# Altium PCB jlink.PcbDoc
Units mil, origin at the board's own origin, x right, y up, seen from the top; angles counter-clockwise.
Board outline 2620 x 1025 mil, 2 copper layers (Top Layer, Bottom Layer); 30 components, 28 nets, 122 pads, 66 vias.
Unrouted connection lines stored in the file: 1.
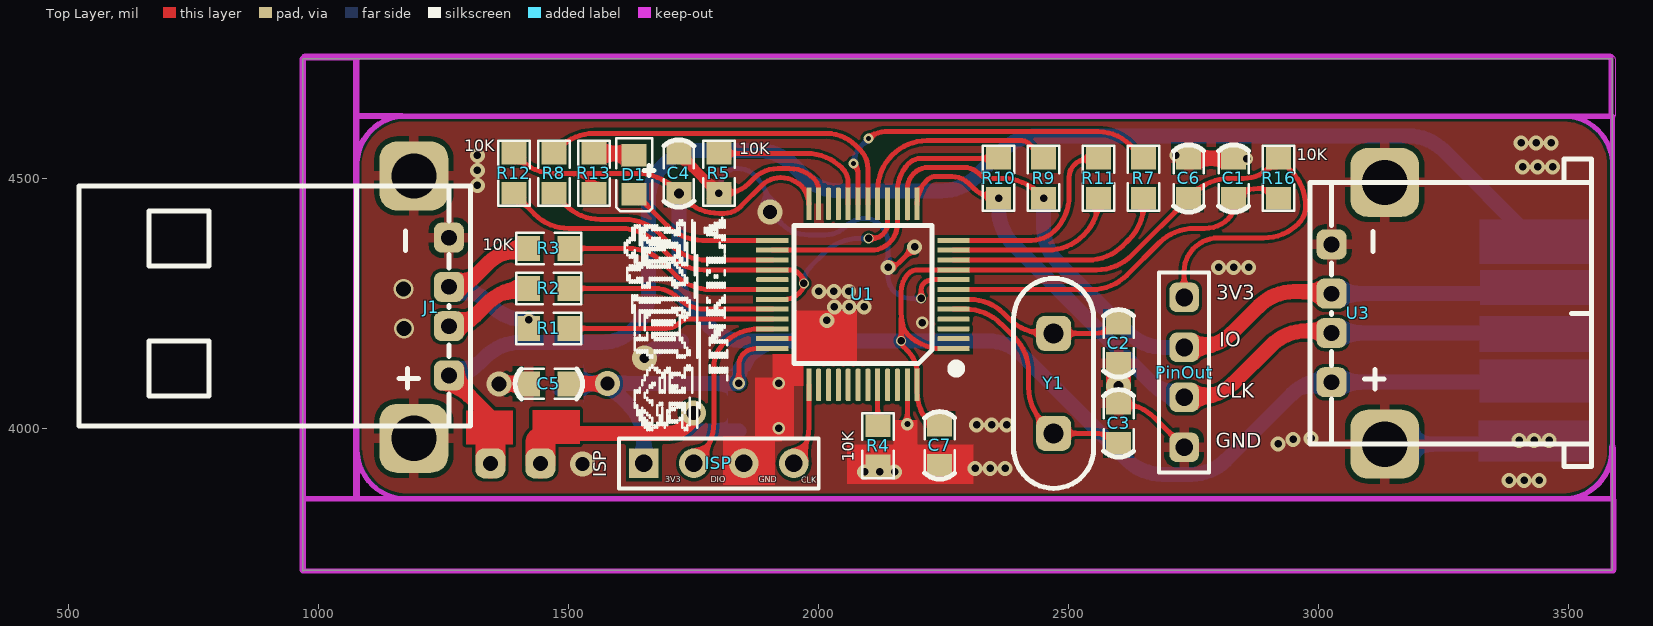
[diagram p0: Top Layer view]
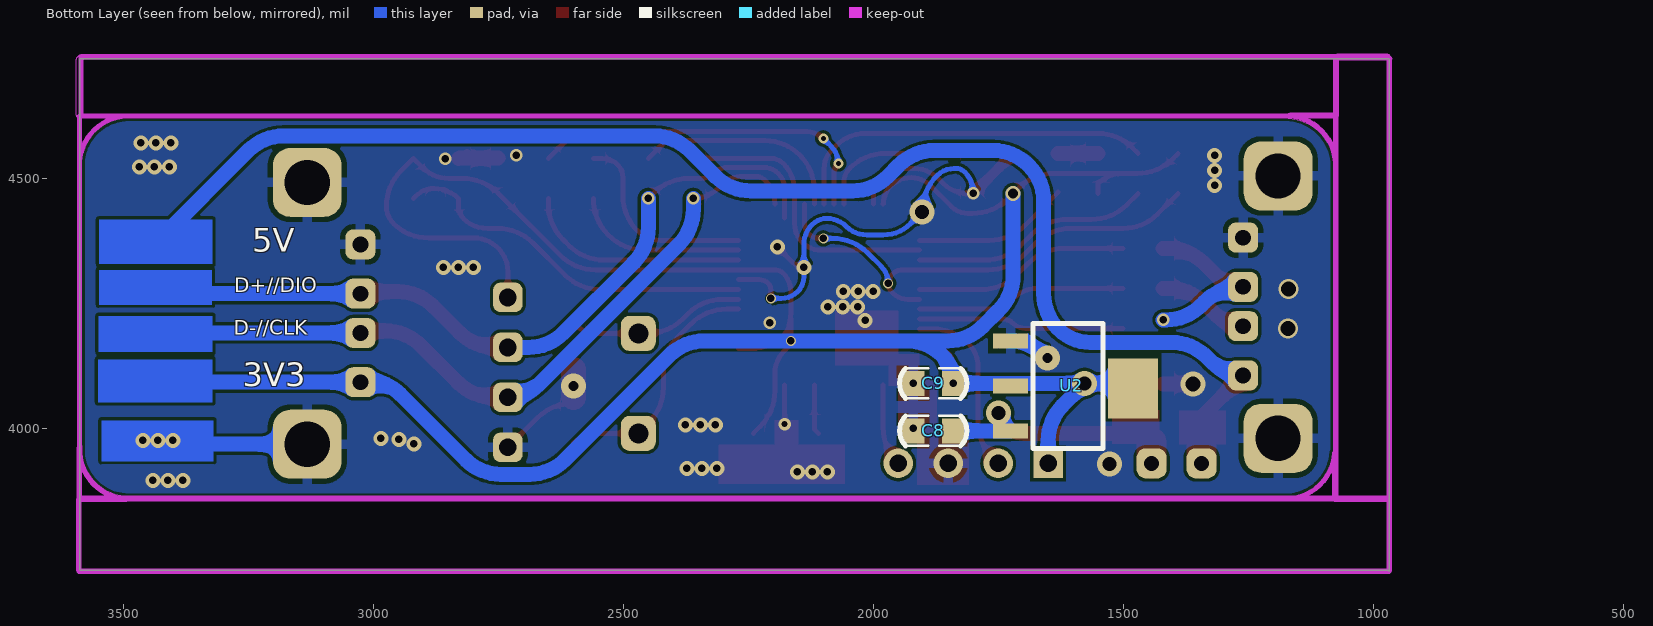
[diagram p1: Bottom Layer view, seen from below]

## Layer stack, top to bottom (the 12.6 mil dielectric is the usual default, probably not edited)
Top Solder: solder mask 0.4, Solder Resist, Dk 3.5
Top Layer: signal copper 1.4
Dielectric1: dielectric 12.6, FR-4, Dk 4.8
Bottom Layer: signal copper 1.4
Bottom Solder: solder mask 0.4, Solder Resist, Dk 3.5

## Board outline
969,3716 969,4741 3589,4741 3589,3717 970,3717
cut-out: 3589,4534 ccw(c3490.5,4527.5) 3484,4626 3589,4626
cut-out: 966.45,3712.45 965.45,3713.45 965.47,3713.44 cw(c969,3717) 963.99,3717 963.99,3860 cw(c969,3860) 969,3865.01 3589,3865.01 cw(c3589,3860) 3592.56,3863.53 3592.55,3863.55 3593.55,3862.55 3593.53,3862.56 cw(c3590,3859) 3595.01,3859 3595.01,3717 cw(c3590,3717) 3593.53,3713.44 3593.55,3713.45 3592.55,3712.45 3592.56,3712.47 cw(c3589,3716) 3589,3710.99 970,3710.99 cw(c970,3716)
cut-out: 966.45,3712.45 965.45,3713.45 965.47,3713.44 cw(c969,3717) 963.99,3717 963.99,4741 cw(c969,4741) 965.47,4744.56 965.45,4744.55 968.45,4747.55 968.44,4747.53 cw(c972,4744) 972,4749.02 1074,4749.02 cw(c1074,4744) 1077.56,4747.53 1077.55,4747.55 1079.55,4745.55 1079.53,4745.56 cw(c1076,4742) 1081.02,4742 1081.02,3860 cw(c1076,3860) 1070.98,3860 1070.98,4738.98 974.08,4738.98 974.01,4738.92 974.01,3719.01 cw(c970,3716) 975.01,3716 cw(c970,3716)
cut-out: 965.47,3713.44 cw(c969,3717) 963.99,3717 963.99,4741 cw(c969,4741) 965.47,4744.56 965.45,4744.55 968.45,4747.55 968.44,4747.53 cw(c972,4744) 972,4749.02 1074,4749.02 cw(c1074,4744) 1077.56,4747.53 1077.55,4747.55 1079.55,4745.55 1079.53,4745.56 cw(c1076,4742) 1081.02,4742 1081.02,3860 cw(c1076,3860) 1076,3854.99 974.01,3854.99 974.01,3719.01 cw(c970,3716) 975.01,3716 cw(c970,3716) 966.45,3712.45
cut-out: 972.55,4737.45 974.08,4738.98 1070.98,4738.98 1070.98,4626 ccw(c1076,4626) 1076,4620.98 3589,4620.98 ccw(c3589,4626) 3592.56,4622.47 3592.55,4622.45 3593.55,4623.45 3593.53,4623.44 ccw(c3590,4627) 3595.01,4627 3595.01,4740 ccw(c3590,4740) 3593.53,4743.56 3593.55,4743.55 3589.55,4747.55 3589.56,4747.53 ccw(c3586,4744) 3586,4749.02 972,4749.02 ccw(c972,4744) 968.44,4747.53 968.45,4747.55 965.45,4744.55 ccw(c969,4741)
cut-out: 3589,4534 ccw(c3490.5,4527.5) 3484,4626 3589,4626
cut-out: 3497,3854.99 cw(c3497,3860) 3496.67,3865 ccw(c3490.5,3958.5) 3583.98,3952.17 3583.98,3965 cw(c3589,3965) 3589,3970.01 cw(c3589,3965) 3594,3965.33 cw(c3490.5,3958.5) 3594.23,3958.5 cw(c3490.5,3958.5) 3594.01,3951.84 3594.01,3862.01 cw(c3590,3859) 3595.01,3859 cw(c3590,3859) 3586.99,3854.99
cut-out: 1183,3860 cw(c1176.5,3958.5) 1078,3952 1078,3860
cut-out: 1070.98,4534.16 1070.98,4738.98 974.08,4738.98 972.55,4737.45 cw(c969,4741) 965.45,4744.55 968.45,4747.55 968.44,4747.53 cw(c972,4744) 972,4749.02 1074,4749.02 cw(c1074,4744) 1077.56,4747.53 1077.55,4747.55 1079.55,4745.55 1079.53,4745.56 cw(c1076,4742) 1081.02,4742 1081.02,4631.02 1168,4631.02 cw(c1168,4626) 1173.02,4626 cw(c1168,4626) 1168.33,4621 ccw(c1174.5,4527.5) 1081.02,4533.83 1081.02,4521 cw(c1076,4521) 1071,4520.67 cw(c1174.5,4527.5)

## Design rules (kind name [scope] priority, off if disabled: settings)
Clearance [All] p1: gap=6 ignorepadtopadclearanceinfootprint=FALSE except(0: Arc-Hole Track-Hole SMDPad-Hole THPad-Hole Via-Hole Fill-Hole Poly-Hole Region-Hole Text-Hole)
HoleSize [All] p1: absolutevalues=TRUE maxlimit=100 minlimit=12 maxpercent=80.000 minpercent=20.000
HoleToHoleClearance [All] p1: gap=5 allowstackedmicrovias=TRUE
MinimumSolderMaskSliver [All] p1: minsoldermaskwidth=0
PolygonConnect PolygonConnect_1 [isVia] p1: connectstyle=Direct reliefconductorwidth=10 reliefentries=4 polygonreliefangle="90 Angle" airgapwidth=10
PolygonConnect [All] p2: connectstyle=Relief reliefconductorwidth=20 reliefentries=4 polygonreliefangle="90 Angle" airgapwidth=10
RoutingVias [All] p1: holewidth=15 width=25 viastyle="Through Hole" minholewidth=15 minwidth=20 maxholewidth=200 maxwidth=50
SilkToSilkClearance [All] p1: silktosilkclearance=0
SilkToSolderMaskClearance [IsPad] p1: minsilkscreentomaskgap=0 clearancetoexposedcopper=TRUE
SolderMaskExpansion [All] p1: expansion=4
Width [All] p1: maxlimit=100 minlimit=6 preferedwidth=10
25 further rules are at their usual default settings.

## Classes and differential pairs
component class jlink: C1 C2 C3 C4 C5 C6 C7 D1 ISP J1 PinOut R1 R2 R3 R4 R5 R7 R8 R9 R10 R11 R12 R13 R16 U1 U2 Y1

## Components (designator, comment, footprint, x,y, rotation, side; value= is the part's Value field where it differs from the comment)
C1 "104" 0805_cap 2831,4501 r90 top
C2 "22pF" 0805_cap 2601,4171 r270 top
C3 "22pF" 0805_cap 2601,4011 r90 top
C4 "104" 0805_cap 1721,4511 r90 top
C5 "104" 0805_cap 1461,4090 r180 top
C6 "104" 0805_cap 2741,4501 r90 top
C7 "104" 0805_cap 2243,3967 r270 top
C8 "104" 0805_cap 1881,3996 r0 bottom
C9 "104" 0805_cap 1881,4091 r0 bottom
D1 "" LED-0805 1631,4507 r270 top
ISP "" HDR1X4#1 1651,3931 r0 top
J1 "" USB_A公头 1011,4251 r0 top
PinOut "" HDR1X4#2 2732,4263 r270 top
R1 "100" 0805 1461,4201 r0 top
R2 "100" 0805 1461,4281 r0 top
R3 "10K" 0805 1461,4361 r180 top
R4 "10K" 0805 2120,3966 r270 top
R5 "10K" 0805 1801,4511 r270 top
R7 "100" 0805 2651,4501 r270 top
R8 "100" 0805 1471,4511 r270 top
R9 "100" 0805 2451,4501 r90 top
R10 "100" 0805 2361,4501 r90 top
R11 "100" 0805 2561,4501 r270 top
R12 "10K" 0805 1391,4511 r90 top
R13 "100" 0805 1551,4511 r270 top
R16 "10K" 0805 2921,4501 r90 top
U1 "f103c8" LQFP48S 2271,4161 r180 top
U2 "" "AMS1117 3V3 SOT23" 1541,4211 r270 bottom
U3 "" USB_A1ĸ 3192,4250 r180 top
Y1 "" XTAL-8M 2471,4091 r90 top

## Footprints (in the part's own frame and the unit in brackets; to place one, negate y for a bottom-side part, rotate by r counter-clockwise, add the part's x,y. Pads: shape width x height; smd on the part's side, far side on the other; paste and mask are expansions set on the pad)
0805 [mil]
  rect 45x50 smd: 1(-40,0) 2(40,0)
  silkscreen extent -65,-31 65,31, body extent -50,-20 50,20, height 25
0805_cap [mil]
  rect 45x50 smd: 1(-40,0) 2(40,0)
  silkscreen extent -67,-30 67,30, body extent -50,-20 50,20, height 25
"AMS1117 3V3 SOT23" [mil]
  rect 30x70 smd: 1(35,-185) 2(125,-185) 3(215,-185)
  rect 120x100 smd: 2(130,60)
  silkscreen extent 0,-140 250,0, body extent 20,-160 230,20, height 35
HDR1X4#1 [mm] "Connector; Header; 4 Position"
  rect 1.5x1.5 hole 0.9: 1(0,0)
  round 1.5 hole 0.9: 2(2.54,0) 3(5.08,0) 4(7.62,0)
  silkscreen extent -1.27,-1.27 8.89,1.27
HDR1X4#2 [mm] "Connector; Header; 4 Position"
  rrect50% 1.5x1.5 hole 0.9: 1(0,0) 2(2.54,0) 3(5.08,0) 4(7.62,0)
  silkscreen extent -1.27,-1.27 8.89,1.27
LED-0805 [mil]
  rect 45x50 smd: 1(-40,0) 2(37.5,0)
  silkscreen extent -75,-35 72,40, body extent -40,-20 40,20, height 30
LQFP48S [mil] "DPIN-0.5"
  rect 65x10 smd: 1(0.42,0.29) 5(0.42,-78.45) 6(0.42,-98.13) 7(0.42,-117.82) 8(0.42,-137.5) 9(0.42,-157.19) 10(0.42,-176.87) 11(0.42,-196.56) 12(0.42,-216.24) 25(362.63,-216.24) 26(362.63,-196.56) 27(362.63,-176.87) 28(362.63,-157.19) 30(362.63,-117.82) 31(362.63,-98.13) 32(362.63,-78.45) 33(362.63,-58.76) 34(362.63,-39.08) 35(362.63,-19.39) 36(362.63,0.29)
  rrect50% 65x10 smd: 2(0.42,-19.39) 3(0.42,-39.08) 4(0.42,-58.76) 29(362.63,-137.5)
  rect 10x65 smd: 13(73.26,-289.08) 14(92.94,-289.08) 15(112.63,-289.08) 16(132.31,-289.08) 17(152,-289.08) 18(171.68,-289.08) 19(191.37,-289.08) 20(211.05,-289.08) 23(270.11,-289.08) 24(289.79,-289.08) 37(289.79,73.13) 44(152,73.13) 47(92.94,73.13) 48(73.26,73.13)
  rrect50% 10x65 smd: 21(230.74,-289.08) 22(250.42,-289.08) 38(270.11,73.13) 39(250.42,73.13) 40(230.74,73.13) 41(211.05,73.13) 42(191.37,73.13) 43(171.68,73.13) 45(132.31,73.13) 46(112.63,73.13)
  silkscreen extent -10,-246 319,46, body extent 1,-289 366,71, height 30
USB_A1ĸ [mil]
  rrect50% 60x60 hole 31.5: 1(165,156.59) 2(165,58.16) 3(165,-20.58) 4(165,-119)
  rrect50% 137.8x137.8 hole 90.55: 5(58.7,280.61) 5(58.7,-243.02)
  silkscreen extent -355,-290 208,325, body extent -349,-292 208,330, height 297
USB_A公头 [mil] "USB_A公头"
  rrect50% 60x60 hole 31.5: 1(250,-144) 2(250,-45.58) 3(250,33.16) 4(250,131.59)
  rrect50% 137.8x137.8 hole 90.55: 5(180,-270) 5(180,255)
  silkscreen extent -490,-245 293,235
XTAL-8M [mil]
  rrect50% 70x70 hole 40: 1(-100,0) 2(100,0)
  silkscreen extent -210,-80 210,80, body extent -210,-80 210,80, height 110

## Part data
C1 C2 C3 C4 C5 C6 C7 C8 C9: library part Cap, "Capacitor"
D1: library part LED2, "Typical RED, GREEN, YELLOW, AMBER GaAs LED"
ISP PinOut: library part "Header 4", "Header, 4-Pin"
J1: library part USB, "USB-A"
R1 R2 R3 R4 R5 R7 R8 R9 R10 R11 R12 R13 R16: library part Res2, "Resistor"
U1: library part STM32F103C8T6, "STM32 ARM-based 32-bit MCU with 64 Kbytes Flash, 48-pin LQFP, Industrial Temperature"
U2: library part "AMS1117 3V3"
U3: library part USB_ĸ, "USB_ĸ"
Y1: library part XTAL, "Crystal Oscillator"

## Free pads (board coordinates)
  rrect60% 60x60 hole 30: 2(1344,3931) 3(1444,3931)

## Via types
v1: diameter 30, hole 15, Top Layer to Bottom Layer, 39 vias
v2: diameter 25, hole 15, Top Layer to Bottom Layer, 10 vias
v3: diameter 20, hole 15, Top Layer to Bottom Layer, 4 vias
v4: diameter 50, hole 28, Top Layer to Bottom Layer, 4 vias
v5: diameter 40, hole 30, Top Layer to Bottom Layer, 2 vias
v6: diameter 20, hole 10, Top Layer to Bottom Layer, 2 vias
v7: diameter 50, hole 20, Top Layer to Bottom Layer, 2 vias
v8: diameter 30, hole 20, Top Layer to Bottom Layer, 1 vias
v9: diameter 25, hole 12, Top Layer to Bottom Layer, 1 vias
v10: diameter 50, hole 30, Top Layer to Bottom Layer, 1 vias

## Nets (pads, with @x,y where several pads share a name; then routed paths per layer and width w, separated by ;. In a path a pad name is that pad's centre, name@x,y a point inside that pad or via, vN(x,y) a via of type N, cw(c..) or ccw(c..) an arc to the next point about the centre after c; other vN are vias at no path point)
3V3: C4.1 C5.1 C6.1 C7.1 C9.1 ISP.1 PinOut.1 R12.2 R13.2 R16.2 U1.1 U1.9 U1.24 U1.36 U1.48 U2.2 U3.1 | length 5507.4
  Top Layer w10: R12.2 1401.71,4540.29 ccw(c1472.42,4611) 1472.42,4511 1502.72,4511 ; R13.2 1551,4491 ccw(c1502.72,4442.72) 1502.72,4511 ; v8(1721,4471) 1710.29,4481.71 ccw(c1639.58,4411) 1639.58,4511 1502.72,4511 ; C4.1@1731.71,4460.29 ccw(c1802.42,4531) 1802.42,4431 1811,4431 ccw(c1811,4479.28) 1845.14,4445.14 1887.49,4487.49 cw(c1924.56,4450.42) 1924.56,4502.84 cw(c1924.56,4443.44) 1966.56,4485.44 cw(c1931.19,4450.08) U1.24 ; v2(1841,4091) 1841,4126.86 cw(c1875.14,4126.86) 1851,4151 cw(c1874.44,4127.56) 1874.44,4160.71 U1.36 ; C7.1@2241,3991 2227.03,4004.97 cw(c2297.74,4075.68) 2197.74,4075.68 U1.48 2197.74,4111 ccw(c2134.35,4111) 2179.17,4155.83 2170.95,4164.05 cw(c2182.9,4176) v3(2166,4176) 2166,4221 ccw(c2211.87,4221) 2171.7,4198.86 ; U1.1 2246.69,4160.71 cw(c2246.69,4255.82) 2179.43,4188.56 cw(c2211.87,4221) 2171.7,4198.86 ; PinOut.1 2732,4315.13 cw(c2796.87,4315.13) 2736.27,4338.27 cw(c2796.87,4315.13) 2751,4361 2751.49,4361.49 cw(c2801,4311.99) 2774.99,4376.99 cw(c2801,4311.99) 2801,4382 2890.99,4382 ccw(c2890.99,4481.01) 2961,4411 ccw(c2927.2,4444.8) 2975,4444.8 2975,4445.58 ccw(c2875,4445.58) 2945.71,4516.29 R16.2 2902.21,4522.21 cw(c2851,4573.43) 2851,4501 2822.42,4501 ccw(c2822.42,4401) 2751.71,4471.71 C6.1 2627.48,4347.48 cw(c2556.77,4418.19) 2556.77,4318.19 U1.9 2198.36,4318.19 ccw(c2198.36,4293.64) 2181,4311 ccw(c2217.21,4274.79) 2166,4274.79 2166,4232.13 ccw(c2266,4232.13) 2171.7,4198.86
  Top Layer w30: C5.1 1575.59,4090 ccw(c1575.59,4093.41) v4(1578,4091)
  Bottom Layer w20: v2(1841,4091) C9.1@1841,4094.3
  Bottom Layer w30: U2.2@1481,4081 cw(c1505.14,4056.86) 1505.14,4091 v4(1578,4091) ; ISP.1 1651,3976.58 ccw(c1551,3976.58) 1621.71,4047.29 v4(1578,4091) ; v8(1721,4471) 1721,4307.42 ccw(c1821,4307.42) 1750.29,4236.71 1781.71,4205.29 ccw(c1852.42,4276) 1852.42,4176 1933.42,4176 ; v2(1841,4091) v4(1578,4091) ; C9.1@1841,4094.3 cw(c1915.12,4094.3) 1862.71,4146.71 cw(c1933.42,4076) 1933.42,4176 ; U3.1 3389.17,4093.41 ; U3.1@3027,4097.41 3016.83,4097.41 ccw(c3016.83,3997.41) 2946.12,4068.12 2816.45,3938.45 cw(c2745.74,4009.16) 2745.74,3909.16 2688.26,3909.16 cw(c2688.26,4009.16) 2617.55,3938.45 2409.29,4146.71 ccw(c2338.58,4076) 2338.58,4176 v3(2166,4176) 1933.42,4176
GND: C1.2 C2.2 C3.2 C4.2 C5.2 C6.2 C7.2 C8.2 C9.2 ISP.3 J1.4 J1.5 PinOut.4 R4.2 R5.2 U1.8 U1.23 U1.35 U1.47 U2.1 U3.4 U3.5 | length 2801.4
  Top Layer w10: v2(1801,4471) 1812.72,4471 ccw(c1812.72,4539.28) 1861,4491 1871,4501 cw(c1919.28,4452.72) 1919.28,4521 1942.72,4521 cw(c1942.72,4452.72) 1991,4501 cw(c1967.12,4477.12) 2000.89,4477.12 U1.23 ; ISP.3 1891.71,3971.71 ccw(c1821,4042.42) 1921,4042.42 ; U1.35 1938.97,4180.39 ccw(c1938.97,4280.39) 1978.05,4188.34 ccw(c1938.97,4280.39) 2009.68,4209.68 v1(2017,4217) 1977.26,4177.26 ccw(c2016.53,4138) 1961,4138 1961,4119.28 cw(c1941,4119.28) 1955.14,4105.14 cw(c1921,4139.28) v2(1921,4091) 1921,4042.42 ; v2(1921,4001) 1921,4042.42 ; R4.2@2121,3911 2148.77,3938.77 ccw(c2078.06,4009.48) v9(2178.06,4009.48) ; v1(2140,4323) ccw(c2140,4351.97) 2160.49,4331.49 v1(2193,4364) ; U1.47 v9(2178.06,4009.48) ; v3(2206,4261) 2206,4278.93 cw(c2223.07,4278.93) 2211,4291 cw(c2229.12,4272.88) 2228.5,4298.5 cw(c2229.12,4272.88) 2229.12,4298.5 U1.8 ; C7.2@2241,3911 2215.14,3911 cw(c2215.14,3945.14) 2191,3921 cw(c2222.25,3952.25) 2178.06,3952.25 v9(2178.06,4009.48) ; C3.2@2602.58,4051 cw(c2602.58,3951) 2673.29,4021.71 PinOut.4 ; C6.2 C6.2@2752,4542 ; 2780,4541 ccw(c2780,4587.95) 2787.2,4541.55 ccw(c2780,4587.95) 2813.2,4554.75 cw(c2768.57,4478.57) C1.2
  Top Layer w20: C4.2 v2(1801,4471)
  Top Layer w30: v10(1361,4090) C5.2 ; C6.2@2752,4542 2787.2,4541.55 C1.2
  Top Layer w50: C3.2@2601,4063 v7(2601,4086) C2.2@2601,4119
  Bottom Layer w10: v2(1801,4471) 1801,4472.96 cw(c1859.04,4472.96) 1818,4514 cw(c1834.9,4497.1) 1834.9,4521 1839.2,4521 cw(c1839.2,4473.2) 1873,4507 1873.71,4506.29 cw(c1803,4435.58) 1903,4435.58 v4(1903,4434) 1926.37,4410.63 ccw(c1981,4465.25) 1981,4388 2013.96,4388 ccw(c2013.96,4446.04) 2055,4405 cw(c2093.63,4366.37) 2093.63,4421 cw(c2093.63,4379.06) 2123.28,4408.72 cw(c2082.93,4368.36) 2140,4368.36 v1(2140,4323) 2140,4304.1 ccw(c2181.49,4304.1) 2152.15,4274.76 ccw(c2185.38,4307.98) 2185.38,4261 v3(2206,4261)
  Bottom Layer w30: v7(1652,4142) 1657.72,4147.72 cw(c1726,4079.43) U2.1 ; U3.5@3133.3,3969.39 3369.64,3969.39 ccw(c3369.64,3995.36) v1@3388,3977
  other v1: 3382,3897 3412,3897 3442,3897 2093,3914 2123,3914 2153,3914 2314,3921 2344,3921 2374,3921 2920,3970 3402,3977 3432,3977 3462,3977 2950,3979 2986,3981 2317,4008 2347,4008 2377,4008 2032,4244 2062,4244 2092,4244 2001,4275 2031,4275 2061,4275 2801,4323 2831,4323 2861,4323 1318,4487 1318,4517 3409,4524 3439,4524 3469,4524 1318,4547 3406,4572 3436,4572 3466,4572
  other v2: 2208,4212 2857,4540 2715,4547
  other v4: 1528,3930
  other v5: 1171,4201 1170,4280
JTCK/CLK: ISP.4 U1.37 | length 165.1
  Top Layer w10: ISP.4 1951.92,3931.92 ccw(c1881.21,4002.63) 1981.21,4002.63 U1.37
JTMS/IO: ISP.2 U1.34 | length 362.8
  Top Layer w10: ISP.2 1761.71,3941.71 ccw(c1691,4012.42) 1791,4012.42 1791,4123.01 cw(c1858.57,4123.01) 1810.79,4170.79 cw(c1881.5,4100.08) 1881.5,4200.08 U1.34
LED: D1.2 U1.25 | length 312.9
  Top Layer w10: D1.2@1631,4473.5 1697.97,4406.53 ccw(c1768.68,4477.24) 1768.68,4377.24 U1.25
NetD1_1: D1.1 R13.1 | length 80
  Top Layer w30: R13.1 D1.1@1631,4551
NetJ1_2: J1.2 R2.1 | length 183.7
  Top Layer w30: J1.2 ccw(c1261,4281.29) 1314.65,4227.65 1338.71,4251.71 cw(c1409.42,4181) 1409.42,4281 R2.1
NetJ1_3: J1.3 R1.1 R3.2 | length 363.1
  Top Layer w30: J1.3 ccw(c1261,4359.63) 1314.34,4306.25 1339.81,4331.71 cw(c1410.52,4261) 1410.52,4361 R3.2
  Bottom Layer w10: J1.3 J1.3@1266.41,4284.16
  Bottom Layer w30: J1.3@1266.41,4284.16 cw(c1266.41,4184.16) 1337.12,4254.88 1344.71,4247.29 ccw(c1415.42,4318) 1415.42,4218 v2(1421,4218)
NetR4_1: R4.1 U1.44 | length 100.2
  Top Layer w10: R4.1@2111,3991 2119,3999 U1.44
NetR5_1: R5.1 U1.20 | length 329.5
  Top Layer w10: R5.1 1961,4551 1977.05,4551 cw(c1977.05,4451) 2047.76,4521.71 cw(c2018.35,4492.3) 2059.95,4492.3 2059.95,4473.06 U1.20
NRST: C1.1 R16.1 U1.7 | length 741.8
  Top Layer w10: U1.7 2547.4,4278.82 ccw(c2547.4,4378.82) 2618.11,4308.11 2681.71,4371.71 cw(c2752.42,4301) 2752.42,4401 2772.72,4401 ccw(c2772.72,4469.28) 2821,4421 ccw(c2796.86,4445.14) 2831,4445.14 C1.1 cw(c2879.28,4412.72) 2879.28,4481 cw(c2879.28,4428.57) 2916.36,4465.64 R16.1
OSC_IN: C3.1 U1.5 Y1.1 | length 492.4
  Top Layer w10: U1.5 2294.87,4239.45 cw(c2294.87,4139.45) 2365.58,4210.16 2391.71,4184.03 cw(c2321,4113.32) 2421,4113.32 2421,4082.42 ccw(c2521,4082.42) 2450.29,4011.71 Y1.1 2552.72,3991 cw(c2552.72,3922.72) C3.1
OSC_OUT: C2.1 U1.6 Y1.2 | length 355.6
  Top Layer w10: U1.6 2303.08,4259.13 cw(c2303.08,4163.08) 2371,4231 2381.71,4220.29 ccw(c2452.42,4291) 2452.42,4191 Y1.2 2552.72,4191 ccw(c2552.72,4259.28) C2.1
TCKIN>CLK: PinOut.3 R10.1 U1.13 U3.2 | length 1501.4
  Top Layer w10: U1.13 cw(c2264.52,4450.08) 2217.3,4497.3 cw(c2235.89,4478.71) 2235.89,4505 2267.2,4505 cw(c2267.2,4457.2) 2301,4491 2309.79,4482.21 ccw(c2361,4533.43) v2(2361,4461) R10.1@2350.08,4450.08
  Top Layer w30: PinOut.3 2760.58,4063 ccw(c2760.58,4163) 2831.29,4092.29 2905.55,4166.55 cw(c2976.26,4095.84) 2976.26,4195.84 U3.2@3027,4195.84
  Bottom Layer w30: v2(2361,4461) 2361,4439.42 ccw(c2461,4439.42) 2390.29,4368.71 2670.54,4088.46 ccw(c2732,4149.91) PinOut.3 ; U3.2 3379.91,4191.84 cw(c3379.91,4171.91) 3394,4186
TCKOUT: R10.2 U1.15 U1.26 | length 589.6
  Top Layer w10: U1.26 2105.82,4357.56 ccw(c2105.82,4410.04) 2142.88,4372.88 ccw(c2105.82,4410.04) 2142.93,4372.93 ccw(c2105.66,4410.2) 2158.37,4410.2 U1.15 2158.37,4476.37 cw(c2235.63,4476.37) 2160.08,4492.53 cw(c2235.63,4476.37) 2181,4531 cw(c2205.14,4506.86) 2205.14,4541 R10.2
TDIIN: R8.1 U1.18 | length 747.5
  Top Layer w10: R8.1 1482.72,4562.72 cw(c1551,4494.43) 1551,4591 2016.84,4591 cw(c2016.84,4508.52) 2075.16,4566.84 2083.98,4558.02 cw(c2046.96,4521) 2099.32,4521 U1.18
TDIOUT: R8.2 U1.27 | length 479.6
  Top Layer w10: R8.2 1493.71,4448.29 ccw(c1564.42,4519) 1564.42,4419 1612.78,4419 cw(c1612.78,4319) 1683.49,4389.71 1706.04,4367.16 ccw(c1776.75,4437.87) 1776.75,4337.87 U1.27
TDOIN: R12.1 U1.16 U1.28 U1.31 | length 990.8
  Top Layer w10: R12.1 1432.72,4429.28 ccw(c1501,4497.57) 1501,4401 1605.33,4401 cw(c1605.33,4301) 1676.04,4371.71 1700.27,4347.48 ccw(c1770.98,4418.19) 1770.98,4318.19 U1.28 1939.5,4318.19 cw(c1939.5,4259.5) 1951.08,4317.04 cw(c1943.64,4293.64) 1961,4311 1963.93,4308.07 cw(c1946.86,4291) v3(1971,4291) cw(c1946.86,4291) 1963.93,4273.93 1961,4271 cw(c1932.35,4299.65) 1932.35,4259.13 U1.31 ; v3(2101,4381) 2108.49,4381 ccw(c2108.49,4411.19) 2129.83,4389.83 ccw(c2108.46,4411.2) 2138.69,4411.2 U1.16
  Bottom Layer w10: v3(1971,4291) cw(c2019.28,4291) 1985.14,4325.14 2011.71,4351.71 cw(c2082.42,4281) 2082.42,4381 v3(2101,4381)
TMSIN>IO: PinOut.2 R9.1 U1.14 U3.3 | length 1512.3
  Top Layer w10: U1.14@2178.06,4422.25 U1.14 2178.06,4479.75 cw(c2222.25,4479.75) 2191,4511 cw(c2219.97,4482.03) 2219.97,4523 2292.03,4523 cw(c2292.03,4482.03) 2321,4511 ccw(c2345.14,4535.14) 2345.14,4501 2369.58,4501 cw(c2369.58,4401) 2440.29,4471.71 v2(2451,4461)
  Top Layer w30: PinOut.2 2757.58,4163 ccw(c2757.58,4263) 2828.29,4192.29 2881.29,4245.29 cw(c2952,4174.58) 2952,4274.58 U3.3@3027,4274.58
  Bottom Layer w30: v2(2451,4461) 2451,4403.16 ccw(c2551,4403.16) 2480.29,4332.45 2620.45,4192.29 ccw(c2691.16,4263) 2691.16,4163 PinOut.2 ; U3.3 3367.32,4270.58 ccw(c3367.32,4285.68) 3378,4275
TMSOUT: R9.2 U1.17 | length 430.2
  Top Layer w10: U1.17 2119,4478.34 cw(c2217.16,4478.34) 2147.75,4547.75 ; 2147.78,4547.78 cw(c2217.16,4478.34) 2217.16,4576.5 2407.72,4576.5 cw(c2407.72,4557.72) 2421,4571 R9.2
TRESIN: R11.1 U1.12 | length 402.1
  Top Layer w10: U1.12 2426.72,4377.24 ccw(c2426.72,4442.81) 2473.08,4396.45 ccw(c2403.26,4466.27) 2502,4466.27 2502,4503.86 cw(c2536.14,4503.86) 2512,4528 cw(c2543.38,4496.62) 2543.38,4541 R11.1
TRESOUT: R11.2 U1.11 | length 349.9
  Top Layer w10: U1.11 2459.14,4357.56 ccw(c2459.14,4457.56) 2529.85,4386.85 2531.71,4388.71 ccw(c2461,4459.42) 2561,4459.42 R11.2
TRSTIN: R7.1 U1.19 | length 715.6
  Top Layer w10: v6(2071,4531) cw(c2050.16,4510.16) 2079.63,4510.16 U1.19 ; v6(2101,4581) cw(c2133.59,4548.41) 2133.59,4594.5 2561,4594.5 cw(c2561,4506.38) 2623.31,4568.69 R7.1
  Bottom Layer w10: v6(2071,4531) cw(c2119.28,4531) 2085.14,4565.14 v6(2101,4581)
TRSTOUT: R7.2 U1.10 | length 453.9
  Top Layer w10: U1.10 2539.45,4337.87 ccw(c2539.45,4437.87) 2610.16,4367.16 2621.71,4378.71 ccw(c2551,4449.42) 2651,4449.42 R7.2
USBD+: R1.2 U1.33 | length 412.4
  Top Layer w10: R1.2 1696.86,4201 ccw(c1696.86,4235.14) 1721,4211 cw(c1742.16,4189.84) 1742.16,4219.76 U1.33
USBD-: R2.2 U1.32 | length 418.5
  Top Layer w10: R2.2 1672.72,4281 cw(c1672.72,4212.72) 1721,4261 ccw(c1773.03,4313.03) 1773.03,4239.45 U1.32
USBD_EN: R3.1 U1.30 | length 432.8
  Top Layer w10: R3.1 1619.58,4361 cw(c1619.58,4261) 1690.29,4331.71 1713.89,4308.11 ccw(c1784.6,4378.82) 1784.6,4278.82 U1.30
V5.0: C8.1 J1.1 pad.2 pad.3 U2.3 | length 3365.6
  Top Layer w10: 1343,3994 cw(c1340.59,3991.59) 1344,3991.59 ; 1444,3974.1 cw(c1467.9,3974.1) 1451,3991
  Top Layer w25: v4@1750,4020 v4(1750,4032)
  Top Layer w30: J1.1 1347.71,4020.29 ; 1451,3991 1698,3991 ccw(c1698,4046.53) 1737.26,4007.26 v4@1750,4020
  Top Layer w60: pad.2 1344,3991.59 ; pad.3 1444,3974.1
  Bottom Layer w30: J1.1 ccw(c1261,4193.91) 1322.46,4132.46 1333.71,4143.71 cw(c1404.42,4073) 1404.42,4173 1566.23,4173 ccw(c1566.23,4264.2) 1630.67,4199.67 ccw(c1566.23,4264.2) 1630.71,4199.71 ccw(c1560,4270.42) 1660,4270.42 1660,4455.58 cw(c1760,4455.58) 1689.29,4526.29 1690.71,4527.71 cw(c1761.42,4457) 1761.42,4557 1878.58,4557 cw(c1878.58,4457) 1949.29,4527.71 1971.71,4505.29 ccw(c2042.42,4576) 2042.42,4476 2246.03,4476 ccw(c2246.03,4576) 2316.74,4505.29 2368.16,4556.71 cw(c2438.87,4486) 2438.87,4586 3180.58,4586 cw(c3180.58,4486) 3251.29,4556.71 3426.98,4381.02 ; v4(1750,4032) cw(c1721.03,4032) 1741.51,4011.51 U2.3 C8.1 ; 2317.29,4505.29 2320.71,4508.71 ; 3456,4369 3460,4365
pads on no net: U1.2 U1.3 U1.4 U1.21 U1.22 U1.29 U1.38 U1.39 U1.40 U1.41 U1.42 U1.43 U1.45 U1.46

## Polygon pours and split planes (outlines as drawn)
GND on Top Layer "GND_L01_P012" (solid, pour order 12): 3590,3859 cw(c3597.95,3863.71) 3589,3866 3588,4626 1076,4626 1078,3866 3579.34,3864 cw(c3579.34,3850.35) 3589,3860
GND on Bottom Layer "GND_L02_P014" (solid, pour order 14): 1078,3860 cw(c1082.83,3864.83) 1076,3864.83 1076,4626 3576.89,4626 cw(c3576.89,4608.88) 3589,4620.98 cw(c3577.25,4609.73) 3593.52,4609.37 3593.52,3855.15 1089.7,3855.15 cw(c1089.7,3871.7)

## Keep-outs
Keep-Out Layer:
  lines w10: 969,3717 969,4741 ; 969,3717 970,3716 3589,3716 3590,3717 3590,3859 3589,3860 ; 969,3717 969,3860 ; 969,3860 3589,3860 ; 969,3860 969,4741 ; 969,3860 1076,3860 ; 969,4741 972,4744 ; 969,4741 972,4744 ; 972,4744 3586,4744 ; 972,4744 1074,4744 ; 1074,4744 1076,4742 ; 1074,4744 3586,4744 ; 1074,4744 1076,4742 ; 1076,3860 3589,3860 ; 1076,3860 1076,4626 ; 1076,3860 1076,4742 ; 1076,4626 3589,4626 ; 1076,4626 1076,4742 ; 1076,4626 1168,4626 ccw(c1174.5,4527.5) 1076,4521 1076,4626 ; 3586,4744 3586,4626 3484,4626 cw(c3490.5,4527.5) 3589,4534 3589,4626 ; 3589,3860 3589,4626 ; 3589,3860 3589,4626 ; 3589,3860 3589,3965 cw(c3490.5,3958.5) 3497,3860 3589,3860 ; 1078,3860 1183,3860 cw(c1176.5,3958.5) 1078,3952 1078,3860

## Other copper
Top Layer:
  rectangle net GND: 2151,3955 2199,4017.57
  rectangle net GND: 2058,3890 2311,3969
  rectangle net GND: 1809,3888 1913,3986
  rectangle net GND: 1873,3975 1927,4103
  rectangle net GND: 1936,4085.79 1970.11,4133
  rectangle net GND: 1908.37,3983 1951,4149.61
  rectangle net GND: 1950,4126.45 2077.13,4237
  rectangle net V5.0: 1295,3969 1389,4037
  rectangle net V5.0: 1428,3970 1523,4038
Bottom Layer:
  rectangle net TMSIN>IO: 3324,4248 3550,4318
  rectangle net TCKIN>CLK: 3323,4154 3551,4226
  rectangle net V5.0: 3323,4330 3550,4419
  rectangle net 3V3: 3323,4053 3552,4139
  rectangle net GND: 3321,3935 3545,4017

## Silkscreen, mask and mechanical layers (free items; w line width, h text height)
Top Overlay:
  drawing of 379 lines, arcs and shapes, not listed
  text "3V3" at 2796,4248 h50
  text "IO" at 2802,4154 h50
  text "CLK" at 2796,4052 h50
  text "GND" at 2795,3952 h50
  text "ISP" at 1585,3903 h44 r90
  text "3V3" at 1694,3889 h20
  text "DIO" at 1785,3889 h20
  text "GND" at 1881,3889 h20
  text "CLK" at 1966,3888 h20
Bottom Overlay:
  text "5V" at 3243,4338 h80
  text "D+//DIO" at 3279,4263 h50
  text "D-//CLK" at 3280,4178 h50
  text "3V3" at 3262,4069 h80
Top Solder:
  rectangle: 1299,3971 1386,4033
  rectangle: 1431,3972 1507,4033
  text "ゆさ、サイコ" at 3434,4004 h100 r90
Bottom Solder:
  drawing of 3133 lines, arcs and shapes, not listed
  text "Ailike" at 3072,3879 h100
